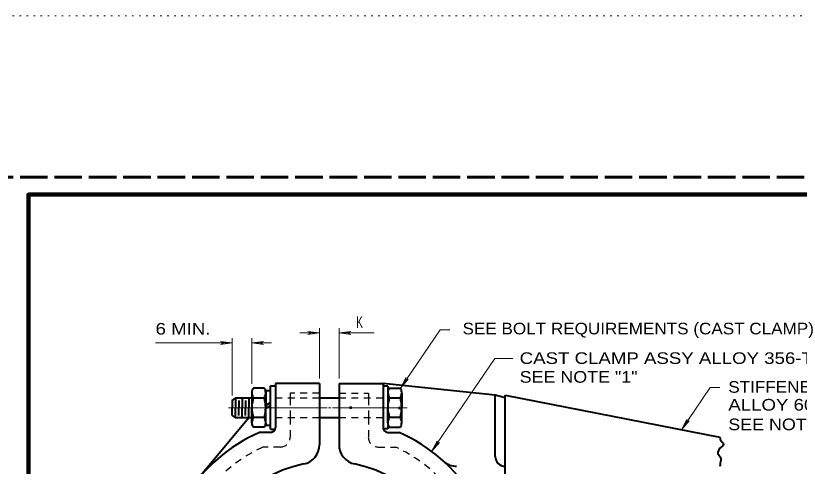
# Model space of a CAD drawing. Extents: x 312583 to 312854, y 144419 to 144597.
# Drawn here: x 312615.7 to 312666.9, y 144567.3 to 144596.8 of the extents above; entities that cross this region are included whole.
import ezdxf

# ---------------------------------------------------------------- set-up
doc = ezdxf.new("R2010")
doc.units = 0
doc.header["$LTSCALE"] = 0.3
doc.header["$PDMODE"] = 32
doc.header["$PDSIZE"] = 0.15
for name, pattern in [('DOTTED', [1.5, 0.3, -1.2]), ('LONG_DASHED', [7.5, 6, -1.5]), ('SHORT_DASHED', [2.7, 1.5, -1.2])]:
    doc.linetypes.add(name, pattern=pattern)
for name, color, linetype, lineweight in [('1', 7, 'Continuous', 35), ('2', 7, 'Continuous', 13), ('62', 7, 'DOTTED', 13), ('63', 7, 'LONG_DASHED', 60)]:
    doc.layers.add(name, color=color, linetype=linetype, lineweight=lineweight)

msp = doc.modelspace()

# ---------------------------------------------------------------- linework, layer by layer
at = {"layer": '1', "lineweight": 40}
for p, q in [((312631.942, 144572.4146), (312631.206, 144572.4146)), ((312632.0263, 144572.2689), (312632.0263, 144572.1386)), ((312632.0263, 144572.2689), (312632.3407, 144572.2689)), ((312632.0263, 144569.9919), (312632.0263, 144572.2689)), ((312632.3407, 144569.7466), (312632.3407, 144572.5756)), ((312632.3407, 144572.5756), (312632.6627, 144572.5756)), ((312632.6627, 144572.7289), (312632.6627, 144569.8539)), ((312635.5377, 144572.7289), (312632.6627, 144572.7289)), ((312635.5377, 144572.7289), (312635.5377, 144568.7116)), ((312636.818, 144572.7289), (312636.818, 144568.7116)), ((312636.818, 144572.7289), (312639.693, 144572.7289)), ((312639.693, 144572.7289), (312639.693, 144569.8616)), ((312640.0073, 144572.5526), (312639.693, 144572.5526)), ((312639.693, 144572.4146), (312639.693, 144569.8616)), ((312640.0073, 144572.5526), (312640.0073, 144569.7696)), ((312640.0917, 144572.4299), (312640.8277, 144572.4299)), ((312631.114, 144571.7706), (312630.0483, 144571.7706)), ((312630.4777, 144571.7706), (312630.4777, 144571.1266)), ((312630.907, 144571.7706), (312630.907, 144571.1266)), ((312631.114, 144572.1386), (312631.114, 144571.1266)), ((312631.9343, 144571.7783), (312631.206, 144571.7783)), ((312632.0263, 144572.1386), (312632.0263, 144571.1266)), ((312636.818, 144571.7706), (312635.5377, 144571.7706)), ((312640.0073, 144572.1539), (312640.0073, 144571.1419)), ((312640.0993, 144571.7936), (312640.8277, 144571.7936)), ((312640.9197, 144572.1463), (312640.9197, 144571.1343)), ((312647.0377, 144567.9526), (312647.0377, 144571.9699)), ((312647.674, 144571.9699), (312661.7347, 144569.2253)), ((312629.8337, 144571.6173), (312629.8337, 144571.1266)), ((312630.263, 144571.6173), (312630.263, 144571.1266)), ((312630.6923, 144571.6173), (312630.6923, 144571.1266)), ((312632.0263, 144571.2876), (312632.3407, 144571.4946)), ((312632.0263, 144571.0729), (312632.3407, 144571.2876)), ((312629.8337, 144570.6436), (312629.8337, 144571.1343)), ((312630.263, 144570.6436), (312630.263, 144571.1343)), ((312630.4777, 144570.4903), (312630.4777, 144571.1343)), ((312630.6923, 144570.6436), (312630.6923, 144571.1343)), ((312630.907, 144570.4903), (312630.907, 144571.1343)), ((312631.114, 144570.1453), (312631.114, 144571.1343)), ((312632.0263, 144570.1376), (312632.0263, 144571.1266)), ((312640.0073, 144570.1529), (312640.0073, 144571.1419)), ((312640.9197, 144570.1606), (312640.9197, 144571.1419)), ((312630.907, 144570.4903), (312627.5643, 144566.4499)), ((312631.114, 144570.4903), (312630.0483, 144570.4903)), ((312631.942, 144570.5056), (312631.206, 144570.5056)), ((312636.818, 144570.4903), (312635.5377, 144570.4903)), ((312640.0917, 144570.5209), (312640.8277, 144570.5209)), ((312631.942, 144569.8616), (312631.206, 144569.8616)), ((312632.0263, 144570.1376), (312632.0263, 144569.9919)), ((312632.0263, 144569.9919), (312632.3407, 144569.9919)), ((312632.3407, 144569.7466), (312632.6627, 144569.7466)), ((312640.0073, 144569.7696), (312639.693, 144569.7696)), ((312640.0917, 144569.8769), (312640.8277, 144569.8769)), ((312632.3407, 144569.5319), (312631.6123, 144569.5319)), ((312640.0073, 144569.5319), (312640.7433, 144569.5319))]:
    msp.add_line(p, q, dxfattribs=at)
at = {"layer": '1', "linetype": 'SHORT_DASHED', "lineweight": 25}
for p, q in [((312635.5377, 144571.7706), (312632.6627, 144571.7706)), ((312633.621, 144571.7706), (312633.621, 144570.4903)), ((312639.693, 144571.7706), (312636.818, 144571.7706)), ((312638.7347, 144571.7706), (312638.7347, 144570.4903)), ((312635.5377, 144570.4903), (312632.6627, 144570.4903)), ((312633.621, 144570.4903), (312633.621, 144569.2099)), ((312639.693, 144570.4903), (312636.818, 144570.4903)), ((312638.7347, 144570.4903), (312638.7347, 144569.2099)), ((312632.9847, 144568.5736), (312631.8193, 144568.5736)), ((312639.371, 144568.5736), (312640.5287, 144568.5736))]:
    msp.add_line(p, q, dxfattribs=at)
at = {"layer": '1', "lineweight": 158}
msp.add_lwpolyline([(312616.5, 144423.1446), (312616.5, 144585.0846), (312849, 144585.0846)], dxfattribs=at)
at = {"layer": '1', "lineweight": 40}
for points in [[(312647.674, 144571.7859), (312647.0377, 144571.9699), (312639.693, 144572.7289)], [(312629.8337, 144571.6173), (312630.0483, 144571.7706), (312630.0483, 144571.1266)], [(312647.674, 144559.3276), (312647.674, 144567.3086), (312647.674, 144571.9699)], [(312629.8337, 144570.6436), (312630.0483, 144570.4903), (312630.0483, 144571.1343)]]:
    msp.add_lwpolyline(points, dxfattribs=at)
at = {"layer": '1', "linetype": 'SHORT_DASHED', "lineweight": 25}
for points in [[(312635.5377, 144572.0849), (312633.621, 144572.0849), (312633.621, 144571.7706)], [(312636.818, 144572.0849), (312638.7347, 144572.0849), (312638.7347, 144571.7706)]]:
    msp.add_lwpolyline(points, dxfattribs=at)
at = {"layer": '1', "lineweight": 40}
for centre, radius, start, end in [((312631.6417, 144572.1215), 0.5262, 145.8703, 178.33743), ((312631.4968, 144572.1215), 0.5262, 1.66257, 34.1297), ((312640.5369, 144572.1343), 0.5262, 145.8703, 178.33743), ((312640.3919, 144572.1343), 0.5262, 1.66257, 34.1297), ((312633.8327, 144571.0742), 2.7192, 164.99798, 178.595), ((312632.5894, 144572.3756), 1.5067, 191.77014, 203.36365), ((312630.5491, 144572.3756), 1.5067, 336.63635, 348.22986), ((312629.3058, 144571.0742), 2.7192, 1.405, 15.00202), ((312642.7278, 144571.087), 2.7192, 164.99798, 178.595), ((312641.4845, 144572.3884), 1.5067, 191.77014, 203.36365), ((312639.4443, 144572.3884), 1.5067, 336.63635, 348.22986), ((312638.201, 144571.087), 2.7192, 1.405, 15.00202), ((312633.8327, 144571.2076), 2.7192, 181.405, 195.00202), ((312629.3058, 144571.2076), 2.7192, 344.99798, 358.595), ((312642.7278, 144571.2204), 2.7192, 181.405, 195.00202), ((312638.201, 144571.2204), 2.7192, 344.99798, 358.595), ((312632.5894, 144569.9062), 1.5067, 156.63635, 168.22986), ((312630.5491, 144569.9062), 1.5067, 11.77014, 23.36365), ((312641.4845, 144569.919), 1.5067, 156.63635, 168.22986), ((312639.4443, 144569.919), 1.5067, 11.77014, 23.36365), ((312631.6417, 144570.1603), 0.5262, 181.66257, 214.1297), ((312631.4968, 144570.1603), 0.5262, 325.8703, 358.33743), ((312632.3432, 144569.8514), 0.3194, 270, 0), ((312640.0099, 144569.8514), 0.3194, 180, 270), ((312640.5369, 144570.1731), 0.5262, 181.66257, 214.1297), ((312640.3919, 144570.1731), 0.5262, 325.8703, 358.33743), ((312636.1766, 144559.325), 11.1806, 114.08876, 180), ((312636.1766, 144559.325), 11.1806, 0, 65.9072), ((312647.6766, 144567.95), 0.6389, 180, 270), ((312636.1766, 144559.325), 8.3056, 101.53815, 180), ((312636.1766, 144559.325), 8.3056, 0, 78.46185), ((312644.5066, 144568.5889), 1.2778, 228.03811, 270)]:
    msp.add_arc(centre, radius, start, end, dxfattribs=at)
at = {"layer": '1', "linetype": 'SHORT_DASHED', "lineweight": 25}
for centre, radius, start, end in [((312632.9821, 144569.2125), 0.6389, 270, 0), ((312639.371, 144569.2125), 0.6389, 180, 270), ((312636.1766, 144559.325), 10.2222, 115.21037, 180), ((312636.1766, 144559.325), 10.2222, 0, 64.78963)]:
    msp.add_arc(centre, radius, start, end, dxfattribs=at)
at = {"layer": '1', "lineweight": 40}
msp.add_spline([(312661.7347, 144569.2253), (312661.7577, 144569.0566), (312661.9647, 144568.7423), (312661.7807, 144568.5353), (312661.6273, 144568.3359), (312661.6043, 144568.1519), (312661.7807, 144567.8683), (312661.7807, 144567.7149), (312661.7347, 144567.3086)], degree=3, dxfattribs=at)
at = {"layer": '2'}
for p, q in [((312635.5377, 144576.0333), (312634.2573, 144576.0333)), ((312634.771, 144576.1253), (312635.0163, 144576.0333)), ((312635.5377, 144576.0333), (312634.771, 144576.1253)), ((312634.771, 144575.9413), (312635.0163, 144576.0333)), ((312635.5377, 144576.0333), (312634.771, 144575.9413)), ((312635.5377, 144573.0433), (312635.5377, 144576.3553)), ((312636.818, 144573.0433), (312636.818, 144576.3553)), ((312636.818, 144576.0333), (312637.5847, 144576.1253)), ((312639.118, 144576.0333), (312636.818, 144576.0333)), ((312636.818, 144576.0333), (312637.5847, 144575.9413)), ((312637.5847, 144576.1253), (312637.3393, 144576.0333)), ((312637.5847, 144575.9413), (312637.3393, 144576.0333)), ((312629.8337, 144575.3816), (312624.817, 144575.3816)), ((312629.067, 144575.4736), (312629.3123, 144575.3816)), ((312629.8337, 144575.3816), (312629.067, 144575.4736)), ((312629.067, 144575.2819), (312629.3123, 144575.3816)), ((312629.8337, 144575.3816), (312629.067, 144575.2819)), ((312629.8337, 144571.9393), (312629.8337, 144575.6959)), ((312631.114, 144572.7059), (312631.114, 144575.6959)), ((312631.114, 144575.3816), (312631.8807, 144575.4736)), ((312632.3943, 144575.3816), (312631.114, 144575.3816)), ((312631.114, 144575.3816), (312631.8807, 144575.2819)), ((312631.8807, 144575.4736), (312631.6353, 144575.3816)), ((312631.8807, 144575.2819), (312631.6353, 144575.3816)), ((312642.8747, 144568.2746), (312647.0147, 144574.3543)), ((312647.0147, 144574.3543), (312648.1953, 144574.3543)), ((312640.8277, 144572.4299), (312641.1803, 144573.1199)), ((312640.8277, 144572.4299), (312641.3413, 144573.0126)), ((312641.1803, 144573.1199), (312641.119, 144572.8669)), ((312641.3413, 144573.0126), (312641.119, 144572.8669)), ((312636.036, 144571.1266), (312629.5807, 144571.1266)), ((312636.1357, 144571.1266), (312636.2813, 144571.1266)), ((312636.381, 144571.1266), (312641.28, 144571.1266)), ((312659.2123, 144569.6929), (312659.565, 144570.3829)), ((312659.2123, 144569.6929), (312659.726, 144570.2756)), ((312659.565, 144570.3829), (312659.5037, 144570.1299)), ((312659.726, 144570.2756), (312659.5037, 144570.1299)), ((312642.8747, 144568.2746), (312643.2273, 144568.9646)), ((312642.8747, 144568.2746), (312643.3883, 144568.8573)), ((312643.2273, 144568.9646), (312643.1737, 144568.7116)), ((312643.3883, 144568.8573), (312643.1737, 144568.7116))]:
    msp.add_line(p, q, dxfattribs=at)
for points in [[(312640.8277, 144572.4299), (312643.4267, 144576.2479), (312644.0707, 144576.2479)], [(312659.2123, 144569.6929), (312661.0983, 144572.4606), (312661.7347, 144572.4606)]]:
    msp.add_lwpolyline(points, dxfattribs=at)
at = {"layer": '2', "lineweight": 40}
for centre, start, end in [((312634.2599, 144568.7148), 281.53696, 0), ((312638.0932, 144568.7148), 180, 258.46304)]:
    msp.add_arc(centre, 1.2778, start, end, dxfattribs=at)
at = {"layer": '2'}
for p in [(312637.5847, 144571.1419), (312640.7817, 144571.1266)]:
    msp.add_point(p, dxfattribs=at)
at = {"layer": '62'}
msp.add_line((312601.2, 144596.7846), (312853.5, 144596.7846), dxfattribs=at)
at = {"layer": '63'}
msp.add_line((312851.75, 144586.2246), (312583.526, 144586.2246), dxfattribs=at)

# ---------------------------------------------------------------- texts
at = {"layer": '2'}
for s, width, p in [('K', 0.65, (312637.9364, 144576.3574)), ('6 MIN.', 1.2, (312624.8154, 144575.9258)), ('SEE BOLT REQUIREMENTS (CAST CLAMP)', 1.1, (312644.8959, 144575.9414)), ('CAST CLAMP ASSY ALLOY 356-T6', 1.2, (312648.6323, 144574.0056)), ('SEE NOTE "1"', 1.15, (312648.6323, 144572.779)), ('STIFFENERS ALUM.', 1.1, (312662.279, 144572.1223)), ('ALLOY 6061-T6', 1.2, (312662.279, 144570.956)), ('SEE NOTE "1"', 1.15, (312662.279, 144569.674))]:
    msp.add_text(s, height=0.76, dxfattribs=dict(at, width=width)).set_placement(p)

doc.saveas('drawing.dxf')
